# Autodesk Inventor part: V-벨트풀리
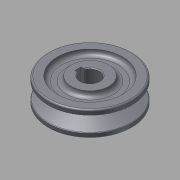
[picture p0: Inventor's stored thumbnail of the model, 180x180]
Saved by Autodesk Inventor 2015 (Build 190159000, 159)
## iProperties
Created: 2015-12
Part Number: V-벨트풀리
Material: 강철, 연강
Document SubType Name: Modeling
Designer: mdu
Density: 7.86 g/cm^3
Appearance: 강철
Author: mdu
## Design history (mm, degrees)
sketch "주 스케치"
  geometry: L1 (0, 16)-(27, 16); L2 (27, 16)-(27, 12.861); L3 (27, 12.861)-(16, 9.498); L4 (16, 9.498)-(16, 6.502); L5 (16, 6.502)-(27, 3.139); L6 (27, 3.139)-(27, 0); L7 (27, 0)-(0, 0); L8 (25, 12.25)-(25, 3.75); L9 (16, 8)-(25, 8); L10 (27, 12.861)-(27, 3.139); L11 (0, -3)-(0, 18) reference; L12 (0, 0)-(0, 16)
  constraints: 22 end point, 5 perpendicular, 2 collinear, 2 midpoint, 2 point on line, 1 parallel
  dimensions: "d0" = 8.5 distance of L8.start L8.end (= da_Bw); "d1" = 34 deg angle of L3 L5 (= da_Alfa); "d2" = 2 distance between parallel lines of L2 L8 (= da_c); "d6" = 16 distance between parallel lines of L7 L1 (computed from d5, da_ng, da_Sg); "d21" = 50 diameter of L8 L11 (= da_Dw); "d25" = 11 distance between parallel lines of L4 L10 (= da_Hd); "d27" = 8 distance between parallel lines of L7 L9 (= da_Se)
node "벨트 평면"
revolve "본체" stored, may be unused: angle "d7" = 90 deg
revolve "그루브" stored, may be unused: angle "d15" = 90 deg
feature "허브 키홈"
fillet "모깎기3" dims "d28" = 0.5, "d29" = 1, "d30" = 1
sketch "스케치2"
  geometry: C1 r 12 at (0, 0); C2 r 21 at (0, 0); 1 further point
  constraints: 2 centre point, 2 coincident
  dimensions: "d31" = 24 diameter of C1; "d32" = 42 diameter of C2
extrude "돌출1" cut sketch "스케치2" distance "d33" = 3; taper "d34" = 0 deg
fillet "모깎기4" dims "d35" = 3
node "작업 평면2"
chamfer "모따기1" distance "d36" = 0.5; stored, may be unused: second distance "d37" = 2, angle "d38" = 45 deg
body "Solid1"
pattern_linear "그루브 패턴" dims "d18" = 12 (= da_Sg)
mirror "대칭1"
other parameters: "d5" = 8 (= da_Se), "da_Bw" = 8.5 [user parameter; used in 1 equation term], "da_Alfa" = 34 deg [user parameter; used in 1 equation term], "da_c" = 2 [user parameter; used in 1 equation term], "da_Dw" = 50 [user parameter; used in 1 equation term], "da_Hd" = 11 [user parameter; used in 1 equation term], "da_Se" = 8 [user parameter; used in 2 equation terms], "da_Sg" = 12 [user parameter; used in 2 equation terms], "da_r1" = 0 [user parameter], "da_r2" = 0 [user parameter], "d24" = 0, "d26" = 0
